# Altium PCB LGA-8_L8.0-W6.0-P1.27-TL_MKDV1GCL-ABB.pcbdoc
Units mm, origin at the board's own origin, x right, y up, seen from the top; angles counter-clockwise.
Board outline 22.65 x 18.76 mm, 2 copper layers (Top Layer, Bottom Layer), stack 0 mm thick; 1 components, 0 nets, 8 pads, 0 vias.
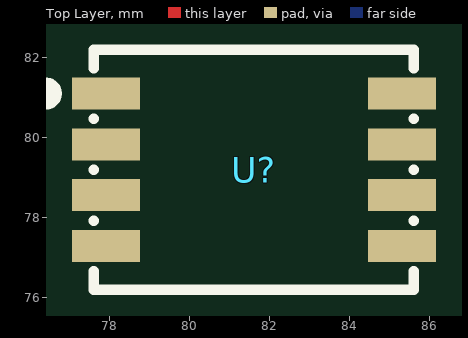
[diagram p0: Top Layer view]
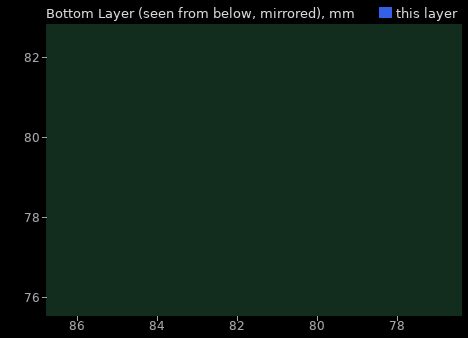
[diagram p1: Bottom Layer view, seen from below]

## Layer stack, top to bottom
Top Layer: signal copper (thickness not stored)
Bottom Layer: signal copper (thickness not stored)

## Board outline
92.5,69.85 69.85,69.85 69.85,88.61 92.5,88.61

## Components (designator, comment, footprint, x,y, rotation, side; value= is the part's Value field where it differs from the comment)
U? "" LGA-8_L8.0-W6.0-P1.27-TL_MKDV1GCL-ABB 81.6,79.2 r0 top

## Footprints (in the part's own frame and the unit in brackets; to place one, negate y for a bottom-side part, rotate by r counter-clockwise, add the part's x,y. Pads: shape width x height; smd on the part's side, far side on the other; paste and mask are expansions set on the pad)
LGA-8_L8.0-W6.0-P1.27-TL_MKDV1GCL-ABB [mm]
  rect 1.7x0.8 smd: 1(-3.7,1.905) 2(-3.7,0.635) 3(-3.7,-0.635) 4(-3.7,-1.905) 5(3.7,-1.905) 6(3.7,-0.635) 7(3.7,0.635) 8(3.7,1.905)
  silkscreen extent -5.4,-3 4,3

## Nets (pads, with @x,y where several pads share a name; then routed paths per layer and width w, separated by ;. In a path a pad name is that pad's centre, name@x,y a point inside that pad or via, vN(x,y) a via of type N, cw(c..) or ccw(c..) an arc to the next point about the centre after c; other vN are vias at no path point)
pads on no net: U?.1 U?.2 U?.3 U?.4 U?.5 U?.6 U?.7 U?.8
